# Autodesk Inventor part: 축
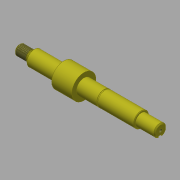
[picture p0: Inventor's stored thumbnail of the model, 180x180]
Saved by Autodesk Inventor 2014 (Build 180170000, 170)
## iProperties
Created: 2016-08
Part Number: 축
Material: 강철, 탄소
Document SubType Name: Modeling
Designer: mduedu
Density: 7.87 g/cm^3
Appearance: 밝은 황색
Author: mduedu
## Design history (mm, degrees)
sketch "스케치1"
  geometry: L1 (-70, 0)-(70, 0); L2 (-70, 0)-(-70, 5); L3 (-70, 5)-(-56, 5); L4 (-56, 5)-(-56, 7.5); L5 (-56, 7.5)-(51, 7.5); L6 (51, 7.5)-(51, 6); L7 (51, 6)-(70, 6); L8 (70, 6)-(70, 0); 2 further points
  constraints: 16 end point, 5 parallel, 2 perpendicular, 1 coincident, 1 horizontal, 1 midpoint
  dimensions: "d0" = 140 distance of L1.start L1.end; "d2" = 14 distance of L2.end L3.end; "d3" = 19 distance of L6.end L7.end; "d4" = 10 diameter of L3 L1; "d5" = 15 diameter of L5 L1; "d6" = 12 diameter of L7 L1
revolve "회전1" sketch "스케치1" stored, may be unused: angle "d7" = 90 deg
sketch "스케치2"
  geometry: L1 (-56, -5)-(-56, 5) reference; L2 (70, -6)-(70, 6) reference; L3 (-56, 0)-(70, 0); L4 (-58, 4.5)-(-58, 5); L5 (-58, 5)-(-56, 5); L6 (-56, 5)-(-56, 4.5); L7 (-58, 4.5)-(-56, 4.5); 1 further point
  constraints: 10 end point, 2 midpoint, 1 parallel, 1 perpendicular, 1 point on line
  dimensions: "d8" = 2 distance of L4.end L5.end; "d10" = 10 diameter of L5 L3; "d11" = 9 diameter of L7 L3
revolve "회전2" sketch "스케치2" stored, may be unused: angle "d12" = 90 deg
node "작업 평면1"
sketch "스케치3"
  geometry: C1 r 12 at (0, 0); 1 further point
  constraints: 1 centre point, 1 coincident
  dimensions: "d15" = 24 diameter of C1
extrude "돌출1" join sketch "스케치3" distance "d16" = 20; taper "d17" = 0 deg
sketch "스케치5"
  geometry: L1 (-70, -5)-(-70, 5) reference; L2 (70, -6)-(70, 6) reference; L3 (-70, 0)-(70, 0); L4 (-6, 7.5)-(51, 7.5) reference; L5 (15.15, 7.5)-(14, 7.5); L6 (14, 7.5)-(14, 7.15); L7 (14, 7.15)-(15.15, 7.15); L8 (15.15, 7.15)-(15.15, 7.5); 1 further point
  constraints: 10 end point, 2 midpoint, 2 parallel, 1 horizontal, 1 perpendicular, 1 point on line
  dimensions: "d19" = 56 distance between parallel lines of L6 L2; "d20" = 1.15 distance between parallel lines of L8 L6; "d21" = 14.3 diameter of L7 L3
revolve "회전3" sketch "스케치5" stored, may be unused: angle "d22" = 90 deg
node "작업 평면3"
sketch "스케치6"
  geometry: L1 (6.5, 2)-(-9.5, 2); L2 (-9.5, 2)-(-9.5, -2); L3 (-9.5, -2)-(6.5, -2); L4 (-9.5, 6)-(-9.5, -6) reference; A1 r 2 centre (6.5, 0) between (6.5, -2) and (6.5, 2); 2 further points
  constraints: 6 end point, 2 midpoint, 2 point on circle, 2 tangent, 1 centre point, 1 horizontal, 1 horizontal alignment, 1 parallel, 1 perpendicular
  dimensions: "d23" = 4 distance between parallel lines of L3 L1; "d62" = 18 dimension on A1 L2
extrude "돌출2" cut sketch "스케치6" distance "d25" = 2.5; taper "d26" = 0 deg
feature "스레드1" dims "d27" = 10, "d28" = 0
chamfer "모따기5" distance "d41" = 0.5; stored, may be unused: second distance "d42" = 2, angle "d43" = 45 deg
chamfer "모따기6" distance "d44" = 0.5; stored, may be unused: second distance "d45" = 2, angle "d46" = 45 deg
chamfer "모따기7" distance "d47" = 1; stored, may be unused: second distance "d48" = 2, angle "d49" = 45 deg
chamfer "모따기8" distance "d50" = 1; stored, may be unused: second distance "d51" = 2, angle "d52" = 45 deg
sketch "스케치8"
  geometry: 1 further point
hole "구멍1" sketch "스케치8" at (2, 3.5) diameter "d53" = 3.242; stored, may be unused: countersink angle "d57" = 90 deg, drill point angle "d59" = 120 deg; dims "d54" = 10, "d55" = 4, "d56" = 2, "d58" = 12
node "솔리드1"
other parameters: "d13" = -44
